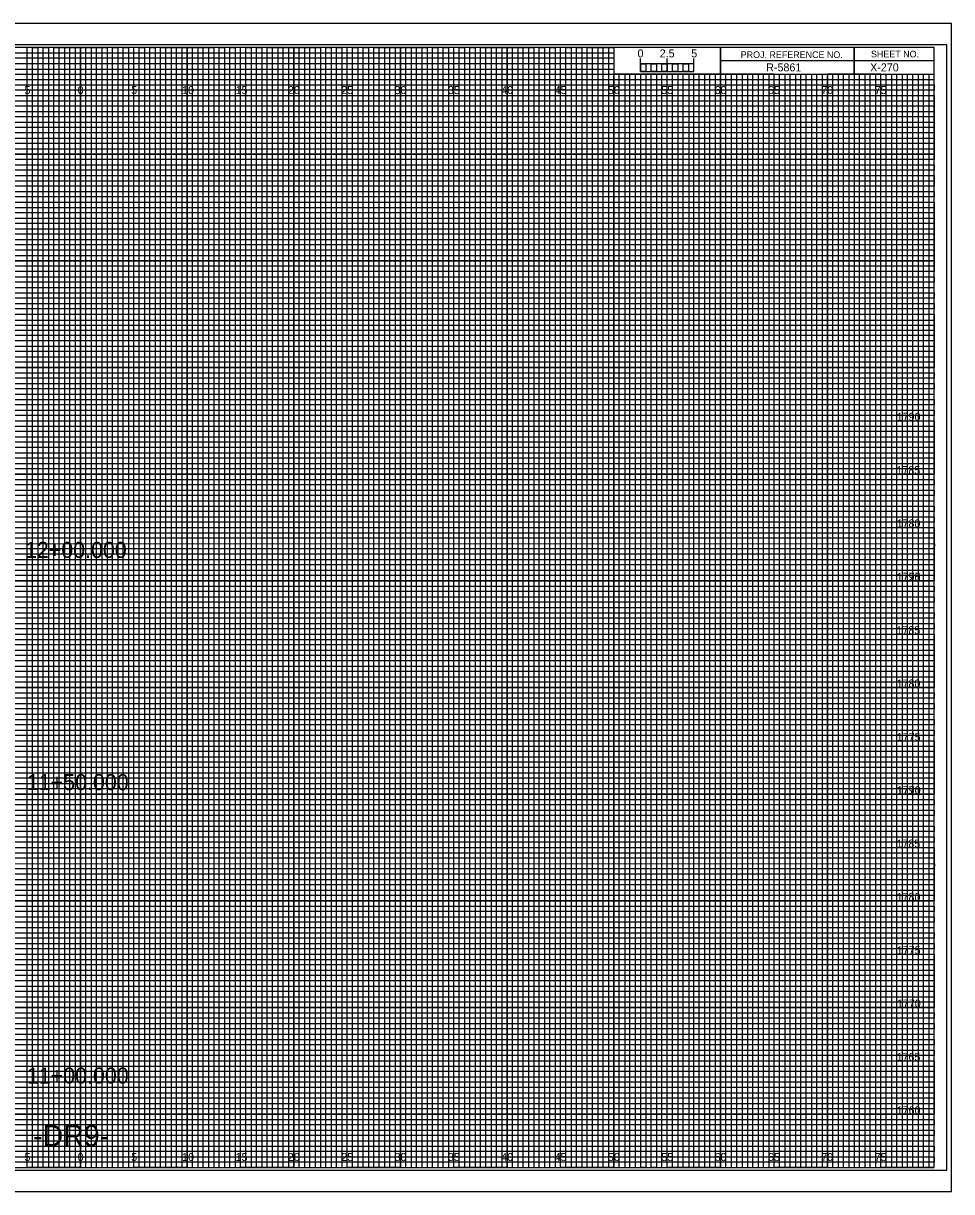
# Model space of a CAD drawing. Extents: x -7 to 162, y -2 to 217.
# Drawn here: x 74.6 to 161.7, y 107.7 to 217.2 of the extents above; entities that cross this region are included whole.
import ezdxf

# ---------------------------------------------------------------- set-up
doc = ezdxf.new("R2010")
doc.units = 0
for name, color, linetype in [('Prop Horizontal Alignment', 7, 'Continuous'), ('Prop XS Alignment Label', 7, 'Continuous'), ('Prop XS Bar Scale Labels', 7, 'Continuous'), ('Prop XS Project Number', 7, 'Continuous'), ('Prop XS Sheet Number', 7, 'Continuous'), ('Raster_Level_0', 7, 'Continuous'), ('Scratch_Level_3', 7, 'Continuous'), ('Sheet Cross Section CELL', 7, 'Continuous'), ('Sheet Cross Section Grid Major CELL', 7, 'Continuous'), ('Sheet Cross Section Grid Middle CELL', 7, 'Continuous'), ('Sheet Cross Section Grid Minor 1 CELL', 7, 'Continuous'), ('Sheet Cross Section Grid Minor 2 CELL', 7, 'Continuous'), ('Sheet Cross Section Scale CELL', 7, 'Continuous'), ('Sheet Cutting Line CELL', 7, 'Continuous'), ('Sheet DOT Grid CELL', 7, 'Continuous'), ('Sheet Plot Border Inside CELL', 7, 'Continuous'), ('Sheet Plot Border Outside CELL', 7, 'Continuous')]:
    doc.layers.add(name, color=color, linetype=linetype)

msp = doc.modelspace()

# ---------------------------------------------------------------- linework, layer by layer
at = {"layer": 'Sheet Cross Section CELL'}
for p, q in [((152.5, 215), (152.5, 212.5)), ((152.5, 212.5), (152.5, 215)), ((160, 213.75), (140, 213.75)), ((140, 213.75), (140, 212.5)), ((140, 212.5), (160, 212.5))]:
    msp.add_line(p, q, dxfattribs=at)
for points in [[(160, 215), (0, 215), (0, 110), (160, 110)], [(140, 215), (130, 215), (130, 212.52), (140, 212.52)], [(160, 215), (140, 215), (140, 212.5), (160, 212.5)]]:
    msp.add_lwpolyline(points, close=True, dxfattribs=at)
at = {"layer": 'Sheet Cross Section Grid Major CELL'}
for p, q in [((75, 215), (70, 215)), ((75, 110), (75, 215)), ((85, 215), (80, 215)), ((80, 215), (80, 110)), ((85, 110), (85, 215)), ((95, 215), (90, 215)), ((90, 215), (90, 110)), ((95, 110), (95, 215)), ((105, 215), (100, 215)), ((100, 215), (100, 110)), ((105, 110), (105, 215)), ((115, 215), (110, 215)), ((110, 215), (110, 110)), ((115, 110), (115, 215)), ((125, 215), (120, 215)), ((120, 215), (120, 110)), ((125, 110), (125, 215)), ((130, 215), (130, 110)), ((135, 110), (135, 212.5)), ((145, 212.5), (140, 212.5)), ((140, 212.5), (140, 110)), ((145, 110), (145, 212.5)), ((155, 212.5), (150, 212.5)), ((150, 212.5), (150, 110)), ((155, 110), (155, 212.5)), ((80, 110), (75, 110)), ((90, 110), (85, 110)), ((100, 110), (95, 110)), ((110, 110), (105, 110)), ((120, 110), (115, 110)), ((130, 110), (125, 110)), ((140, 110), (135, 110)), ((150, 110), (145, 110)), ((160, 110), (155, 110)), ((160, 110), (160, 110))]:
    msp.add_line(p, q, dxfattribs=at)
for points in [[(0, 210), (160, 210), (160, 205), (0, 205)], [(0, 200), (160, 200), (160, 195), (0, 195)], [(0, 190), (160, 190), (160, 185), (0, 185)], [(0, 180), (160, 180), (160, 175), (0, 175)], [(0, 170), (160, 170), (160, 165), (0, 165)], [(0, 160), (160, 160), (160, 155), (0, 155)], [(0, 150), (160, 150), (160, 145), (0, 145)], [(0, 140), (160, 140), (160, 135), (0, 135)], [(0, 130), (160, 130), (160, 125), (0, 125)], [(0, 120), (160, 120), (160, 115), (0, 115)]]:
    msp.add_lwpolyline(points, dxfattribs=at)
at = {"layer": 'Sheet Cross Section Grid Middle CELL'}
for points in [[(72.5, 110), (77.5, 110), (77.5, 215), (82.5, 215), (82.5, 110), (87.5, 110), (87.5, 215), (92.5, 215), (92.5, 110), (97.5, 110), (97.5, 215), (102.5, 215), (102.5, 110), (107.5, 110), (107.5, 215), (112.5, 215), (112.5, 110), (117.5, 110), (117.5, 215), (122.5, 215), (122.5, 110), (127.5, 110), (127.5, 215), (129.97, 215), (130, 215), (130, 212.5), (132.5, 212.5), (132.5, 110), (137.5, 110), (137.5, 212.5), (142.5, 212.5), (142.5, 110), (147.5, 110), (147.5, 212.5), (152.5, 212.5), (152.5, 110), (157.5, 110), (157.5, 212.5)], [(0, 212.5), (137.5, 212.5)], [(0, 202.5), (160, 202.5), (160, 207.5), (0, 207.5)], [(0, 192.5), (160, 192.5), (160, 197.5), (0, 197.5)], [(0, 182.5), (160, 182.5), (160, 187.5), (0, 187.5)], [(0, 172.5), (160, 172.5), (160, 177.5), (0, 177.5)], [(0, 162.5), (160, 162.5), (160, 167.5), (0, 167.5)], [(0, 152.5), (160, 152.5), (160, 157.5), (0, 157.5)], [(0, 142.5), (160, 142.5), (160, 147.5), (0, 147.5)], [(0, 132.5), (160, 132.5), (160, 137.5), (0, 137.5)], [(0, 122.5), (160, 122.5), (160, 127.5), (0, 127.5)], [(0, 112.5), (160, 112.5), (160, 117.5), (0, 117.5)]]:
    msp.add_lwpolyline(points, dxfattribs=at)
at = {"layer": 'Sheet Cross Section Grid Minor 1 CELL'}
for p, q in [((0, 214.5), (130, 214.5)), ((130, 213.99), (0, 213.99)), ((130, 214.5), (130, 213.99)), ((0, 213.5), (130, 213.5)), ((130, 212.94), (0, 212.94)), ((130, 213.5), (130, 212.94)), ((0, 212), (160, 212))]:
    msp.add_line(p, q, dxfattribs=at)
for points in [[(0, 211.5), (135, 211.5), (160, 211.5), (160, 211), (0, 211)], [(0, 210.5), (160, 210.5), (160, 209.5), (0, 209.5)], [(0, 209), (160, 209), (160, 208.5), (0, 208.49)], [(0, 208), (160, 208), (160, 207), (0, 207)], [(0, 206.5), (160, 206.5), (160, 206), (0, 206)], [(0, 205.5), (160, 205.5), (160, 204.5), (0, 204.5)], [(0, 204), (160, 204), (160, 203.5), (0, 203.5)], [(0, 203), (160, 203), (160, 202), (0, 202)], [(0, 201.5), (160, 201.5), (160, 201), (0, 201)], [(0, 200.5), (160, 200.5), (160, 199.5), (0, 199.5)], [(0, 199), (160, 199), (160, 198.5), (0, 198.5)], [(0, 198), (160, 198), (160, 196.97), (160, 196.5), (160, 196), (0, 196)], [(0, 197), (160, 197), (160, 196.5), (0, 196.5)], [(0, 195.5), (160, 195.5), (160, 194.5), (0, 194.52)], [(0, 194.52), (160, 194.5), (160, 194), (0, 194)], [(0, 193.5), (160, 193.5), (160, 193), (0, 193)], [(0, 192), (160, 192), (160, 191.5), (0, 191.5)], [(0, 191), (160, 191), (160, 190.5), (0, 190.5)], [(-0.04, 189.44), (160, 189.44), (160, 188.94), (-0.04, 188.94)], [(0, 188.5), (160, 188.5), (160, 188), (0, 188)], [(0, 187), (160, 187), (160, 186.5), (0, 186.5)], [(0, 186), (160, 186), (160, 185.5), (0, 185.5)], [(0, 184.5), (160, 184.5), (160, 184), (0, 184)], [(0, 183.5), (160, 183.5), (160, 183), (0, 183)], [(0, 182), (160, 182), (160, 181.5), (0, 181.5)], [(0, 181), (160, 181), (160, 180.5), (0, 180.5)], [(0, 179.5), (160, 179.5), (160, 178.99), (0, 179)], [(0, 178.5), (160, 178.5), (160, 178), (0, 178)], [(0, 177), (160, 177), (160, 176.5), (0, 176.5)], [(0, 176), (160, 176), (160, 175.5), (0, 175.5)], [(0, 174.5), (160, 174.5), (160, 174), (0, 174)], [(0, 173.5), (160, 173.5), (160, 173), (0, 173)], [(0, 172), (160, 172), (160, 171.5), (0, 171.5)], [(0, 171), (160, 171), (160, 170.5), (0, 170.5)], [(0, 169.5), (160, 169.5), (160, 169), (0, 169)], [(0, 168.5), (160.03, 168.46), (160, 168), (0, 168)], [(0, 167), (160, 167), (160, 166.5), (0, 166.5)], [(0, 166), (160, 166), (160, 165.5), (0, 165.5)], [(0, 164.5), (160, 164.5), (160, 164), (0, 164)], [(0, 163.5), (160, 163.5), (160, 163), (0, 163)], [(0, 162), (160, 162), (160, 161.5), (0, 161.5)], [(0, 161), (160, 161), (160, 160.5), (0, 160.5)], [(0, 159.5), (160, 159.5), (160, 159), (0, 159)], [(0, 158.5), (160, 158.5), (160, 158), (0, 158)], [(0, 157), (160, 157), (160, 156.5), (0, 156.5)], [(0, 156), (160, 156), (160, 155.5), (0, 155.5)], [(0, 154.5), (160, 154.5), (160, 154), (0, 154)], [(0, 153.5), (160, 153.5), (160, 153), (0, 153)], [(0, 152), (160, 152), (160, 151.5), (0, 151.5)], [(0, 151), (160, 151), (160, 150.5), (0, 150.5)], [(0, 149.5), (160, 149.5), (160, 148.99), (0, 149)], [(0, 148.5), (160, 148.5), (160, 148), (0, 148)], [(0, 147), (160, 147), (160, 146.5), (0, 146.5)], [(0, 146), (160, 146), (160, 145.5), (0, 145.5)], [(0, 144.5), (160, 144.5), (160, 144), (0, 144)], [(0, 143.5), (160, 143.5), (160, 143), (0, 143)], [(0, 142), (160, 142), (160, 141.5), (0, 141.5)], [(0, 141), (160, 141), (160, 140.5), (0, 140.5)], [(0, 139.5), (160, 139.5), (160, 139), (0, 139)], [(0, 138.5), (160.03, 138.46), (160, 138), (0, 138)], [(0, 137), (160, 137), (160, 136.5), (0, 136.5)], [(0, 136), (160, 136), (160, 135.5), (0, 135.5)], [(0, 134.5), (160, 134.5), (160, 134), (0, 134)], [(0, 133.5), (160, 133.5), (160, 133), (0, 133)], [(0, 132), (160, 132), (160, 131.5), (0, 131.5)], [(0, 131), (160, 131), (160, 130.5), (0, 130.5)], [(0, 129.5), (160, 129.5), (160, 129), (0, 129)], [(0, 128.5), (160, 128.5), (160, 128), (0, 128)], [(0, 127), (160, 127), (160, 126.5), (0, 126.5)], [(0, 126), (160, 126), (160, 125.5), (0, 125.5)], [(0, 124.5), (160, 124.5), (160, 124), (0, 124)], [(0, 123.5), (160, 123.5), (160, 123), (0, 123)], [(0, 122), (160, 122), (160, 121.5), (0, 121.5)], [(0, 121), (160, 121), (160, 120.5), (0, 120.5)], [(0, 119.5), (160, 119.5), (160, 119), (0, 119)], [(0, 118.5), (160, 118.5), (160, 118), (0, 118)], [(0, 117), (160, 117), (160, 116.5), (0, 116.5)], [(0, 116), (160, 116), (160, 115.5), (0, 115.5)], [(0, 114.5), (160, 114.5), (160, 114), (0, 114)], [(0, 113.5), (160, 113.5), (160, 113), (0, 113)], [(0, 112), (160, 112), (160, 111.5), (0, 111.5)], [(0, 111), (160, 111), (160, 110.5), (0, 110.5)]]:
    msp.add_lwpolyline(points, dxfattribs=at)
at = {"layer": 'Sheet Cross Section Grid Minor 2 CELL'}
for p, q in [((133.5, 212.5), (133, 212.5)), ((133, 212.5), (133, 110)), ((133.5, 110), (133.5, 212.5)), ((134.5, 212.5), (134, 212.5)), ((134, 212.5), (134, 110)), ((134.5, 110), (134.5, 212.5)), ((133, 110), (132.5, 110)), ((134, 110), (133.5, 110))]:
    msp.add_line(p, q, dxfattribs=at)
for points in [[(75, 110), (75.5, 110), (75.5, 215), (76, 215), (76, 110)], [(76, 110), (76.5, 110), (76.5, 215), (77, 215), (77, 110)], [(77.5, 110), (78, 110), (78, 215), (78.5, 215), (78.5, 110)], [(78.5, 110), (79, 110), (79, 215), (79.5, 215), (79.5, 110)], [(80, 110), (80.5, 110), (80.5, 215), (81, 215), (81, 110)], [(81, 110), (81.5, 110), (81.5, 215), (82, 215), (82, 110)], [(82.5, 110), (83, 110), (83, 215), (83.5, 215), (83.5, 110)], [(83.5, 110), (84, 110), (84, 215), (84.5, 215), (84.5, 110)], [(85, 110), (85.5, 110), (85.5, 215), (86, 215), (86, 110)], [(86, 110), (86.5, 110), (86.5, 215), (87, 215), (87, 110)], [(87.5, 110), (88, 110), (88, 215), (88.5, 215), (88.5, 110)], [(88.5, 110), (89, 110), (89, 215), (89.5, 215), (89.5, 110)], [(90, 110), (90.5, 110), (90.5, 215), (91, 215), (91, 110)], [(91, 110), (91.5, 110), (91.5, 215), (92, 215), (92, 110)], [(92.5, 110), (93, 110), (93, 215), (93.5, 215), (93.5, 110)], [(93.5, 110), (94, 110), (94, 215), (94.5, 215), (94.5, 110)], [(95, 110), (95.5, 110), (95.5, 215), (96, 215), (96, 110)], [(96, 110), (96.5, 110), (96.5, 215), (97, 215), (97, 110)], [(97.5, 110), (98, 110), (98, 215), (98.5, 215), (98.5, 110)], [(98.5, 110), (99, 110), (99, 215), (99.5, 215), (99.5, 110)], [(100, 110), (100.5, 110), (100.5, 215), (101, 215), (101, 110)], [(101, 110), (101.5, 110), (101.5, 215), (102, 215), (102, 110)], [(102.5, 110), (103, 110), (103, 215), (103.5, 215), (103.5, 110)], [(103.5, 110), (104, 110), (104, 215), (104.5, 215), (104.5, 110)], [(105, 110), (105.5, 110), (105.5, 215), (106, 215), (106, 110)], [(106, 110), (106.5, 110), (106.5, 215), (107, 215), (107, 110)], [(107.5, 110), (108, 110), (108, 215), (108.5, 215), (108.5, 110)], [(108.5, 110), (109, 110), (109, 215), (109.5, 215), (109.5, 110)], [(110, 110), (110.5, 110), (110.5, 215), (111, 215), (111, 110)], [(111, 110), (111.5, 110), (111.5, 215), (112, 215), (112, 110)], [(112.5, 110), (113, 110), (113, 215), (113.5, 215), (113.5, 110)], [(113.5, 110), (114, 110), (114, 215), (114.5, 215), (114.5, 110)], [(115, 110), (115.5, 110), (115.5, 215), (116, 215), (116, 110)], [(116, 110), (116.5, 110), (116.5, 215), (117, 215), (117, 110)], [(117.5, 110), (118, 110), (118, 215), (118.5, 215), (118.5, 110)], [(118.5, 110), (119, 110), (119, 215), (119.5, 215), (119.5, 110)], [(120, 110), (120.5, 110), (120.5, 215), (121, 215), (121, 110)], [(121, 110), (121.5, 110), (121.5, 215), (122, 215), (122, 110)], [(122.5, 110), (123, 110), (123, 215), (123.5, 215), (123.5, 110)], [(123.5, 110), (124, 110), (124, 215), (124.5, 215), (124.5, 110)], [(125, 110), (125.5, 110), (125.5, 215), (126, 215), (126, 110)], [(126, 110), (126.5, 110), (126.5, 215), (127, 215), (127, 110)], [(127.5, 110), (128, 110), (128, 215), (128.5, 215), (128.5, 110)], [(128.5, 110), (129, 110), (129, 215), (129.5, 215), (129.5, 110)], [(130, 110), (130.5, 110), (130.5, 212.5), (131.01, 212.5), (131.01, 110)], [(131, 110), (131.5, 110), (131.5, 212.5), (132, 212.5), (132, 110)], [(135, 110), (135.49, 110), (135.49, 212.5), (136, 212.5), (136, 110)], [(136, 110), (136.5, 110), (136.5, 212.5), (137.03, 212.5), (137.03, 110)], [(137.5, 110), (138, 110), (138, 212.5), (138.5, 212.5), (138.5, 110)], [(138.5, 110), (139, 110), (139, 212.5), (139.5, 212.5), (139.5, 110)], [(140, 110), (140.5, 110), (140.5, 212.5), (141, 212.5), (141, 110)], [(141, 110), (141.5, 110), (141.5, 212.5), (142, 212.5), (142, 110)], [(142.5, 110), (143, 110), (143, 212.5), (143.5, 212.5), (143.5, 110)], [(143.5, 110), (144, 110), (144, 212.5), (144.5, 212.5), (144.5, 110)], [(145, 110), (145.5, 110), (145.5, 212.5), (146, 212.5), (146, 110)], [(146, 110), (146.5, 110), (146.5, 212.5), (147, 212.5), (147, 110)], [(147.5, 110), (148, 110), (148, 212.5), (148.5, 212.5), (148.5, 110)], [(148.5, 110), (149, 110), (149, 212.5), (149.5, 212.5), (149.5, 110)], [(150, 110), (150.5, 110), (150.5, 212.5), (151, 212.5), (151, 110)], [(151, 110), (151.5, 110), (151.5, 212.5), (152, 212.5), (152, 110)], [(152.5, 110), (153, 110), (153, 212.5), (153.5, 212.5), (153.5, 110)], [(153.5, 110), (154, 110), (154, 212.5), (154.5, 212.5), (154.5, 110)], [(155, 110), (155.5, 110), (155.5, 212.5), (156, 212.5), (156, 110)], [(156, 110), (156.5, 110), (156.5, 212.5), (157, 212.5), (157, 110)], [(157.5, 110), (158, 110), (158, 212.5), (158.5, 212.5), (158.5, 110)], [(158.5, 110), (159, 110), (159, 212.5), (159.5, 212.5), (159.5, 110)]]:
    msp.add_lwpolyline(points, dxfattribs=at)
at = {"layer": 'Sheet Cross Section Scale CELL'}
for p, q in [((132.5, 212.75), (132.5, 213.95)), ((132.5, 213.45), (132.5, 213.95)), ((135, 212.75), (135, 213.95)), ((137.5, 212.75), (137.5, 213.95)), ((137.5, 213.45), (137.5, 213.95))]:
    msp.add_line(p, q, dxfattribs=at)
for points in [[(137.5, 213.45), (132.5, 213.45), (132.5, 212.75), (137.5, 212.75)], [(132.5, 213.45), (133, 213.45), (133, 212.75), (132.5, 212.75)], [(133.5, 213.45), (134, 213.45), (134, 212.75), (133.5, 212.75)], [(134.5, 213.45), (135, 213.45), (135, 212.75), (134.5, 212.75)], [(135.5, 213.45), (136, 213.45), (136, 212.75), (135.5, 212.75)], [(136.5, 213.45), (137, 213.45), (137, 212.75), (136.5, 212.75)]]:
    msp.add_lwpolyline(points, close=True, dxfattribs=at)
at = {"layer": 'Sheet Cutting Line CELL'}
for p, q in [((161.65, 217.25), (-6.7, 217.25)), ((-6.7, 107.75), (161.65, 107.75))]:
    msp.add_line(p, q, dxfattribs=at)
at = {"layer": 'Sheet DOT Grid CELL'}
for p, q in [((75, 110), (75, 215)), ((80, 110), (80, 215)), ((85, 110), (85, 215)), ((90, 110), (90, 215)), ((95, 110), (95, 215)), ((100, 110), (100, 215)), ((105, 110), (105, 215)), ((110, 110), (110, 215)), ((115, 110), (115, 215)), ((120, 110), (120, 215)), ((125, 110), (125, 215)), ((130, 110), (130, 212.34)), ((135, 110), (135, 212.34)), ((140, 110), (140, 212.34)), ((145, 110), (145, 212.34)), ((150, 110), (150, 212.34)), ((155, 110), (155, 212.34)), ((0, 210), (160, 210)), ((0, 205), (160, 205)), ((0, 200), (160, 200)), ((0, 195), (160, 195)), ((0, 190), (160, 190)), ((0, 185), (160, 185)), ((0, 180), (160, 180)), ((0, 175), (160, 175)), ((0, 170), (160, 170)), ((0, 165), (160, 165)), ((0, 160), (160, 160)), ((0, 155), (160, 155)), ((0, 150), (160, 150)), ((0, 145), (160, 145)), ((0, 140), (160, 140)), ((0, 135), (160, 135)), ((0, 130), (160, 130)), ((0, 125), (160, 125)), ((0, 120), (160, 120)), ((0, 115), (160, 115))]:
    msp.add_line(p, q, dxfattribs=at)
at = {"layer": 'Sheet Plot Border Inside CELL'}
msp.add_lwpolyline([(-5.4, 109.75), (161.2, 109.75), (161.2, 215.25), (-5.4, 215.25)], close=True, dxfattribs=at)
at = {"layer": 'Sheet Plot Border Outside CELL'}
msp.add_lwpolyline([(-6.7, 107.75), (161.65, 107.75), (161.65, 217.25), (-6.7, 217.25)], close=True, dxfattribs=at)

# ---------------------------------------------------------------- texts
at = {"layer": 'Prop Horizontal Alignment'}
for s, p in [('12+00.000', (74.79, 167.15)), ('11+50.000', (74.97, 145.38)), ('11+00.000', (74.97, 117.88))]:
    msp.add_text(s, height=1.5, dxfattribs=at).set_placement(p)
at = {"layer": 'Prop XS Alignment Label'}
msp.add_text('-DR9-', height=2, dxfattribs=at).set_placement((75.55, 112))
at = {"layer": 'Prop XS Bar Scale Labels'}
for s, p in [('2.5', (134.29, 214.06)), ('5', (137.24, 214.06))]:
    msp.add_text(s, height=0.75, dxfattribs=at).set_placement(p)
at = {"layer": 'Prop XS Project Number'}
msp.add_text('R-5861', height=0.75, dxfattribs=at).set_placement((144.27, 212.75))
at = {"layer": 'Prop XS Sheet Number'}
msp.add_text('X-270', height=0.75, dxfattribs=at).set_placement((154.01, 212.75))
at = {"layer": 'Raster_Level_0'}
for s, p in [('5', (74.74, 210.62)), ('0', (79.73, 210.62)), ('0', (79.73, 210.62)), ('5', (84.74, 210.62)), ('10', (89.52, 210.62)), ('15', (94.53, 210.62)), ('20', (99.43, 210.62)), ('25', (104.44, 210.62)), ('30', (109.43, 210.62)), ('35', (114.44, 210.62)), ('40', (119.43, 210.62)), ('45', (124.44, 210.62)), ('50', (129.43, 210.62)), ('55', (134.44, 210.62)), ('60', (139.43, 210.62)), ('65', (144.44, 210.62)), ('70', (149.43, 210.62)), ('75', (154.44, 210.62)), ('5', (74.74, 110.62)), ('0', (79.73, 110.62)), ('0', (79.73, 110.62)), ('5', (84.74, 110.62)), ('10', (89.52, 110.62)), ('15', (94.53, 110.62)), ('20', (99.43, 110.62)), ('25', (104.44, 110.62)), ('30', (109.43, 110.62)), ('35', (114.44, 110.62)), ('40', (119.43, 110.62)), ('45', (124.44, 110.62)), ('50', (129.43, 110.62)), ('55', (134.44, 110.62)), ('60', (139.43, 110.62)), ('65', (144.44, 110.62)), ('70', (149.43, 110.62)), ('75', (154.44, 110.62))]:
    msp.add_text(s, height=0.75, dxfattribs=at).set_placement(p)
at = {"layer": 'Scratch_Level_3'}
for s, p in [('1790', (156.5, 180)), ('1785', (156.48, 175)), ('1780', (156.49, 170)), ('1790', (156.5, 165)), ('1775', (156.51, 165)), ('1785', (156.48, 160)), ('1780', (156.49, 155)), ('1775', (156.51, 150)), ('1790', (156.5, 145)), ('1770', (156.52, 145)), ('1785', (156.48, 140)), ('1780', (156.49, 135)), ('1775', (156.51, 130)), ('1770', (156.52, 125)), ('1765', (156.49, 120)), ('1760', (156.5, 115))]:
    msp.add_text(s, height=0.75, dxfattribs=at).set_placement(p)
at = {"layer": 'Sheet Cross Section CELL'}
for s, p in [('PROJ. REFERENCE NO.', (141.88, 214)), ('SHEET NO.', (154.09, 214.06))]:
    msp.add_text(s, height=0.625, dxfattribs=at).set_placement(p)
at = {"layer": 'Sheet Cross Section Scale CELL'}
msp.add_text('0', height=0.75, dxfattribs=at).set_placement((132.21, 214.06))

doc.saveas('drawing.dxf')
